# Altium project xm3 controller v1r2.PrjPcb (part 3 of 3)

## Sheet Temperature Sense.SchDoc: Controller
size 492 x 365 mm; OrgAddr3: USA; Page Create Date: March  8, 1995; OrgName: Wolfspeed; OrgAddr1: 535 W Research Center Blvd.; Page Number: 5; Page Size: A; Comment: DualBrandTitleBlock1; Page Count: 8; OrgAddr2: Fayetteville, AR, 72701; Page Name: Temperature Sense; RevCode: V1.2; DsnPath: C:\Users\cnew\Downloads\xm3 controller v1r2-2022-03-14T15-49\xm3 controller v1r2.dsn; SchematicName: SCHEMATIC1; PageName: Temperature Sense; PageSize: A; TopSchematic: True
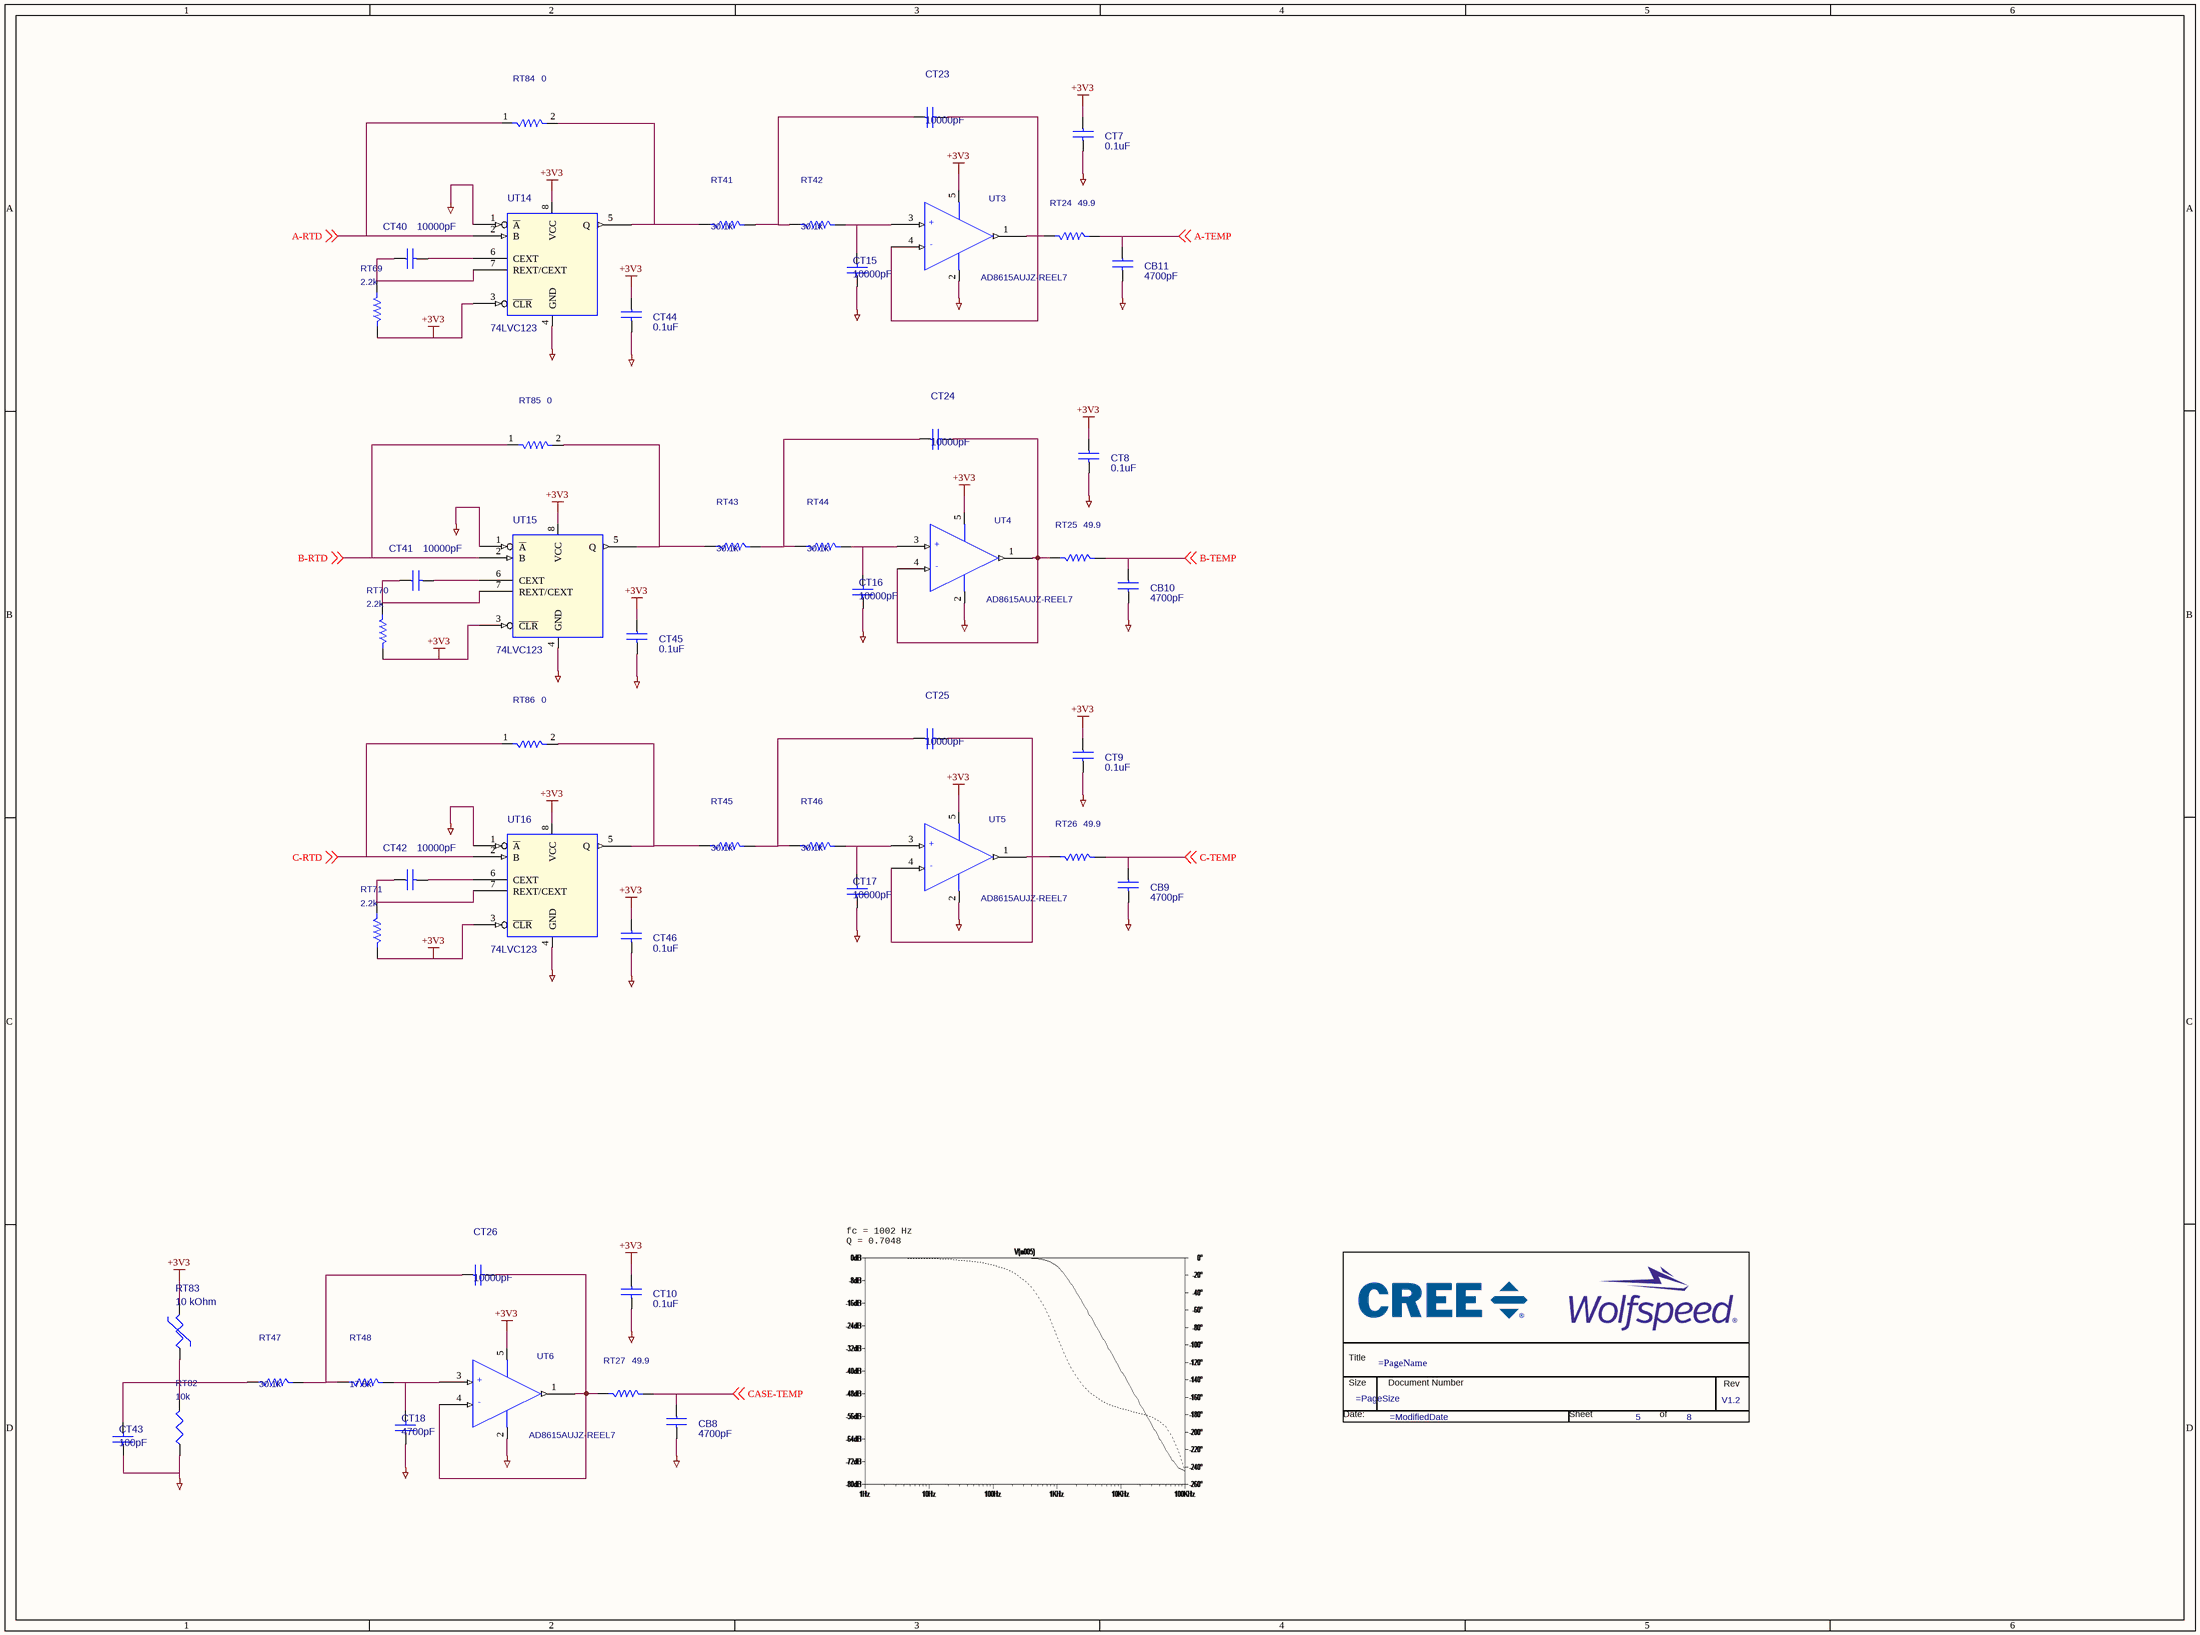
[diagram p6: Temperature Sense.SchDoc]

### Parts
(Parts that share a designator on the sheet are numbered #1, #2 ... from top to bottom, then left to right.)
*#7  Page Count: 8  Page Number: 5  RevCode: V1.2  (hidden comment: DualBrandTitleBlock1)  (graphical)
CB8  4700pF  [c_0603]
CB9  4700pF  [c_0603]
CB10  4700pF  [c_0603]
CB11  4700pF  [c_0603]
CT7  0.1uF  [CAPC1608X87N]
CT8  0.1uF  [CAPC1608X87N]
CT9  0.1uF  [CAPC1608X87N]
CT10  0.1uF  [CAPC1608X87N]
CT15  10000pF  [CAPC1608X90N]
CT16  10000pF  [CAPC1608X90N]
CT17  10000pF  [CAPC1608X90N]
CT18  4700pF  [CAPC1608X90N]
CT23  10000pF  [CAPC1608X90N]
CT24  10000pF  [CAPC1608X90N]
CT25  10000pF  [CAPC1608X90N]
CT26  10000pF  [CAPC1608X90N]
CT40  10000pF  [CAPC1608X90N]
CT41  10000pF  [CAPC1608X90N]
CT42  10000pF  [CAPC1608X90N]
CT43  100pF  [CAPC1608X90N]
CT44  0.1uF  [CAPC1608X87N]
CT45  0.1uF  [CAPC1608X87N]
CT46  0.1uF  [CAPC1608X87N]
RT24  49.9  [RESC1608X55N]
RT25  49.9  [RESC1608X55N]
RT26  49.9  [RESC1608X55N]
RT27  49.9  [RESC1608X55N]
RT41  30.1k  [RESC1608X55N]
RT42  30.1k  [RESC1608X55N]
RT43  30.1k  [RESC1608X55N]
RT44  30.1k  [RESC1608X55N]
RT45  30.1k  [RESC1608X55N]
RT46  30.1k  [RESC1608X55N]
RT47  30.1k  [RESC1608X55N]
RT48  17.8k  [RESC1608X55N]
RT69  2.2k  [RESC1608X55N]
RT70  2.2k  [RESC1608X55N]
RT71  2.2k  [RESC1608X55N]
RT82  10k  [RESC1608X65N]
RT83  10 kOhm  [RESC2012X60N]
RT84  0  [RESC2012X70N]
RT85  0  [RESC2012X70N]
RT86  0  [RESC2012X70N]
UT3  AD8615AUJZ-REEL7  [sot23-5_0_95x2_70p_h1_22]
UT4  AD8615AUJZ-REEL7  [sot23-5_0_95x2_70p_h1_22]
UT5  AD8615AUJZ-REEL7  [sot23-5_0_95x2_70p_h1_22]
UT6  AD8615AUJZ-REEL7  [sot23-5_0_95x2_70p_h1_22]
UT14  74LVC123  [VSSOP8]
UT15  74LVC123  [VSSOP8]
UT16  74LVC123  [VSSOP8]

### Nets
0: CB8.2 CB9.2 CB10.2 CB11.2 CT7.2 CT8.2 CT9.2 CT10.2 CT15.1 CT16.1 CT17.1 CT18.1 CT43.1 CT44.2 CT45.2 CT46.2 RT82.1 UT3.2(V-) UT4.2(V-) UT5.2(V-) UT6.2(V-) UT14.1(~{A}) UT14.4(GND) UT15.1(~{A}) UT15.4(GND) UT16.1(~{A}) UT16.4(GND)
+3V3: CT7.1 CT8.1 CT9.1 CT10.1 CT44.1 CT45.1 CT46.1 RT69.1 RT70.1 RT71.1 RT83.2 UT3.5(V+) UT4.5(V+) UT5.5(V+) UT6.5(V+) UT14.3(~{CLR}) UT14.8(VCC) UT15.3(~{CLR}) UT15.8(VCC) UT16.3(~{CLR}) UT16.8(VCC)
A-RTD: RT84.1 UT14.2(B) ; off-sheet A-RTD
A-TEMP: CB11.1 RT24.2 ; off-sheet A-TEMP
B-RTD: RT85.1 UT15.2(B) ; off-sheet B-RTD
B-TEMP: CB10.1 RT25.2 ; off-sheet B-TEMP
C-RTD: RT86.1 UT16.2(B) ; off-sheet C-RTD
C-TEMP: CB9.1 RT26.2 ; off-sheet C-TEMP
CASE-TEMP: CB8.1 RT27.2 ; off-sheet CASE-TEMP
NetCT15_2: CT15.2 RT42.2 UT3.3(IN+)
NetCT16_2: CT16.2 RT44.2 UT4.3(IN+)
NetCT17_2: CT17.2 RT46.2 UT5.3(IN+)
NetCT18_2: CT18.2 RT48.2 UT6.3(IN+)
NetCT23_1: CT23.1 RT41.2 RT42.1
NetCT23_2: CT23.2 RT24.1 UT3.1(OUT) UT3.4(IN-)
NetCT24_1: CT24.1 RT43.2 RT44.1
NetCT24_2: CT24.2 RT25.1 UT4.1(OUT) UT4.4(IN-)
NetCT25_1: CT25.1 RT45.2 RT46.1
NetCT25_2: CT25.2 RT26.1 UT5.1(OUT) UT5.4(IN-)
NetCT26_1: CT26.1 RT47.2 RT48.1
NetCT26_2: CT26.2 RT27.1 UT6.1(OUT) UT6.4(IN-)
NetCT40_1: CT40.1 RT69.2 UT14.7(REXT/CEXT)
NetCT40_2: CT40.2 UT14.6(CEXT)
NetCT41_1: CT41.1 RT70.2 UT15.7(REXT/CEXT)
NetCT41_2: CT41.2 UT15.6(CEXT)
NetCT42_1: CT42.1 RT71.2 UT16.7(REXT/CEXT)
NetCT42_2: CT42.2 UT16.6(CEXT)
NetCT43_2: CT43.2 RT47.1 RT82.2 RT83.1
NetRT41_1: RT41.1 RT84.2 UT14.5(Q)
NetRT43_1: RT43.1 RT85.2 UT15.5(Q)
NetRT45_1: RT45.1 RT86.2 UT16.5(Q)

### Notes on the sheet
- fc = 1002 Hz
  Q = 0.7048

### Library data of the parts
*#7 = DualBrandTitleBlock1: OrgAddr3: USA; OrgAddr2: Fayetteville, AR, 72701; OrgAddr1: 535 W Research Center Blvd.; OrgName: Wolfspeed; Title: Controller
CB8 = CAP: CAP CER 4700PF 25V X7R 0603; Part Reference: CB8; PART_NUMBER: TMP-889; Manufacturer: Murata Electronics North America; Manufacturer PN: GCM188R71E472KA37D; Company Part Status: New; Dielectric Type: Capacitors; Tolerance: 10%; CLASS: DISCRETE
CB9 = CAP: CAP CER 4700PF 25V X7R 0603; Part Reference: CB9; Manufacturer PN: GCM188R71E472KA37D; Manufacturer: Murata Electronics North America; PART_NUMBER: TMP-889; Company Part Status: New; CLASS: DISCRETE; Tolerance: 10%; Dielectric Type: Capacitors
CB10 = CAP: CAP CER 4700PF 25V X7R 0603; Part Reference: CB10; Manufacturer PN: GCM188R71E472KA37D; Manufacturer: Murata Electronics North America; PART_NUMBER: TMP-889; Company Part Status: New; CLASS: DISCRETE; Tolerance: 10%; Dielectric Type: Capacitors
CB11 = CAP: CAP CER 4700PF 25V X7R 0603; Part Reference: CB11; Manufacturer PN: GCM188R71E472KA37D; Manufacturer: Murata Electronics North America; PART_NUMBER: TMP-889; Company Part Status: New; CLASS: DISCRETE; Tolerance: 10%; Dielectric Type: Capacitors
CT7 = CAP: CAP CER 0.1UF 25V X7R 0603; Part Reference: CT7; PART_NUMBER: TMP-847; Manufacturer: Kemet; Manufacturer PN: C0603C104K3RACTU; Company Part Status: New; Dielectric Type: Capacitors; Tolerance: 10%; CLASS: DISCRETE
CT8 = CAP: CAP CER 0.1UF 25V X7R 0603; Part Reference: CT8; Manufacturer PN: C0603C104K3RACTU; Manufacturer: Kemet; PART_NUMBER: TMP-847; Company Part Status: New; CLASS: DISCRETE; Tolerance: 10%; Dielectric Type: Capacitors
CT9 = CAP: CAP CER 0.1UF 25V X7R 0603; Part Reference: CT9; Manufacturer PN: C0603C104K3RACTU; Manufacturer: Kemet; PART_NUMBER: TMP-847; Company Part Status: New; CLASS: DISCRETE; Tolerance: 10%; Dielectric Type: Capacitors
CT10 = CAP: CAP CER 0.1UF 25V X7R 0603; Part Reference: CT10; PART_NUMBER: TMP-847; Manufacturer: Kemet; Manufacturer PN: C0603C104K3RACTU; Company Part Status: New; Dielectric Type: Capacitors; Tolerance: 10%; CLASS: DISCRETE
CT15 = CAP: CAP CER 10000PF 25V 10% X7R 0603; Part Reference: CT15; Company Part Status: New; Manufacturer PN: CL10B103KA8NNNC; Manufacturer: Samsung Electro-Mechanics America, Inc.; PART_NUMBER: TMP-566; CLASS: DISCRETE; Dielectric Type: Capacitors
CT16 = CAP: CAP CER 10000PF 25V 10% X7R 0603; Part Reference: CT16; Company Part Status: New; PART_NUMBER: TMP-566; Manufacturer: Samsung Electro-Mechanics America, Inc.; Manufacturer PN: CL10B103KA8NNNC; Dielectric Type: Capacitors; CLASS: DISCRETE
CT17 = CAP: CAP CER 10000PF 25V 10% X7R 0603; Part Reference: CT17; Company Part Status: New; PART_NUMBER: TMP-566; Manufacturer: Samsung Electro-Mechanics America, Inc.; Manufacturer PN: CL10B103KA8NNNC; Dielectric Type: Capacitors; CLASS: DISCRETE
CT18 = CAP: CAP CER 4700PF 25V X7R 0603; Part Reference: CT18; Manufacturer PN: GCM188R71E472KA37D; Manufacturer: Murata Electronics North America; PART_NUMBER: TMP-889; CLASS: DISCRETE; Tolerance: 10%; Dielectric Type: Capacitors
CT23 = CAP: CAP CER 10000PF 25V 10% X7R 0603; Part Reference: CT23; Manufacturer PN: CL10B103KA8NNNC; Manufacturer: Samsung Electro-Mechanics America, Inc.; PART_NUMBER: TMP-566; Company Part Status: New; CLASS: DISCRETE; Dielectric Type: Capacitors
CT24 = CAP: CAP CER 10000PF 25V 10% X7R 0603; Part Reference: CT24; PART_NUMBER: TMP-566; Manufacturer: Samsung Electro-Mechanics America, Inc.; Manufacturer PN: CL10B103KA8NNNC; Company Part Status: New; Dielectric Type: Capacitors; CLASS: DISCRETE
CT25 = CAP: CAP CER 10000PF 25V 10% X7R 0603; Part Reference: CT25; PART_NUMBER: TMP-566; Manufacturer: Samsung Electro-Mechanics America, Inc.; Manufacturer PN: CL10B103KA8NNNC; Company Part Status: New; Dielectric Type: Capacitors; CLASS: DISCRETE
CT26 = CAP: CAP CER 10000PF 25V 10% X7R 0603; Part Reference: CT26; Manufacturer PN: CL10B103KA8NNNC; Manufacturer: Samsung Electro-Mechanics America, Inc.; PART_NUMBER: TMP-566; Company Part Status: New; CLASS: DISCRETE; Dielectric Type: Capacitors
CT40 = CAP: CAP CER 10000PF 25V 10% X7R 0603; Part Reference: CT40; PART_NUMBER: TMP-566; Manufacturer: Samsung Electro-Mechanics America, Inc.; Manufacturer PN: CL10B103KA8NNNC; Company Part Status: New; Dielectric Type: Capacitors; CLASS: DISCRETE
CT41 = CAP: CAP CER 10000PF 25V 10% X7R 0603; Part Reference: CT41; PART_NUMBER: TMP-566; Manufacturer: Samsung Electro-Mechanics America, Inc.; Manufacturer PN: CL10B103KA8NNNC; Company Part Status: New; Dielectric Type: Capacitors; CLASS: DISCRETE
CT42 = CAP: CAP CER 10000PF 25V 10% X7R 0603; Part Reference: CT42; PART_NUMBER: TMP-566; Manufacturer: Samsung Electro-Mechanics America, Inc.; Manufacturer PN: CL10B103KA8NNNC; Company Part Status: New; Dielectric Type: Capacitors; CLASS: DISCRETE
CT43 = CAP: CAP CER 100PF 50V 5% NP0 0603; Part Reference: CT43; PART_NUMBER: TMP-455; Manufacturer: Samsung Electro-Mechanics America, Inc; Manufacturer PN: CL10C101JB8NNNC; Company Part Status: New; Dielectric Type: Capacitors; Temperature Coefficient: C0G, NP0; CLASS: DISCRETE
CT44 = CAP: CAP CER 0.1UF 25V X7R 0603; Part Reference: CT44; PART_NUMBER: TMP-847; Manufacturer: Kemet; Manufacturer PN: C0603C104K3RACTU; Company Part Status: New; Dielectric Type: Capacitors; Tolerance: 10%; CLASS: DISCRETE
CT45 = CAP: CAP CER 0.1UF 25V X7R 0603; Part Reference: CT45; PART_NUMBER: TMP-847; Manufacturer: Kemet; Manufacturer PN: C0603C104K3RACTU; Company Part Status: New; Dielectric Type: Capacitors; Tolerance: 10%; CLASS: DISCRETE
CT46 = CAP: CAP CER 0.1UF 25V X7R 0603; Part Reference: CT46; PART_NUMBER: TMP-847; Manufacturer: Kemet; Manufacturer PN: C0603C104K3RACTU; Company Part Status: New; Dielectric Type: Capacitors; Tolerance: 10%; CLASS: DISCRETE
RT24 = RES_Dup1: RES SMD 49.9 OHM 1% 1/10W 0603; Part Reference: RT24; Manufacturer PN: ERJ-3EKF49R9V; Manufacturer: Panasonic Electronic Components; Company Part Status: New; CLASS: DISCRETE; Rated Power: 0.1W, 1/10W; Temperature Coefficient: 100ppm/C
RT25 = RES_Dup1: RES SMD 49.9 OHM 1% 1/10W 0603; Part Reference: RT25; Manufacturer PN: ERJ-3EKF49R9V; Manufacturer: Panasonic Electronic Components; Company Part Status: New; CLASS: DISCRETE; Rated Power: 0.1W, 1/10W; Temperature Coefficient: 100ppm/C
RT26 = RES_Dup1: RES SMD 49.9 OHM 1% 1/10W 0603; Part Reference: RT26; Manufacturer PN: ERJ-3EKF49R9V; Manufacturer: Panasonic Electronic Components; Company Part Status: New; CLASS: DISCRETE; Rated Power: 0.1W, 1/10W; Temperature Coefficient: 100ppm/C
RT27 = RES_Dup1: RES SMD 49.9 OHM 1% 1/10W 0603; Part Reference: RT27; Manufacturer: Panasonic Electronic Components; Manufacturer PN: ERJ-3EKF49R9V; Company Part Status: New; Temperature Coefficient: 100ppm/C; Rated Power: 0.1W, 1/10W; CLASS: DISCRETE
RT41 = RES_Dup1: RES SMD 30.1K OHM 1% 1/10W 0603; Part Reference: RT41; Manufacturer PN: ERJ-3EKF3012V; Manufacturer: Panasonic Electronic Components; PART_NUMBER: TMP-962; Company Part Status: New; CLASS: DISCRETE; Rated Power: 0.1W, 1/10W; Temperature Coefficient: 100ppm/C
RT42 = RES_Dup1: RES SMD 30.1K OHM 1% 1/10W 0603; Part Reference: RT42; Company Part Status: New; Manufacturer PN: ERJ-3EKF3012V; Manufacturer: Panasonic Electronic Components; PART_NUMBER: TMP-962; CLASS: DISCRETE; Rated Power: 0.1W, 1/10W; Temperature Coefficient: 100ppm/C
RT43 = RES_Dup1: RES SMD 30.1K OHM 1% 1/10W 0603; Part Reference: RT43; PART_NUMBER: TMP-962; Manufacturer: Panasonic Electronic Components; Manufacturer PN: ERJ-3EKF3012V; Company Part Status: New; Temperature Coefficient: 100ppm/C; Rated Power: 0.1W, 1/10W; CLASS: DISCRETE
RT44 = RES_Dup1: RES SMD 30.1K OHM 1% 1/10W 0603; Part Reference: RT44; Company Part Status: New; PART_NUMBER: TMP-962; Manufacturer: Panasonic Electronic Components; Manufacturer PN: ERJ-3EKF3012V; Temperature Coefficient: 100ppm/C; Rated Power: 0.1W, 1/10W; CLASS: DISCRETE
RT45 = RES_Dup1: RES SMD 30.1K OHM 1% 1/10W 0603; Part Reference: RT45; PART_NUMBER: TMP-962; Manufacturer: Panasonic Electronic Components; Manufacturer PN: ERJ-3EKF3012V; Company Part Status: New; Temperature Coefficient: 100ppm/C; Rated Power: 0.1W, 1/10W; CLASS: DISCRETE
RT46 = RES_Dup1: RES SMD 30.1K OHM 1% 1/10W 0603; Part Reference: RT46; Company Part Status: New; PART_NUMBER: TMP-962; Manufacturer: Panasonic Electronic Components; Manufacturer PN: ERJ-3EKF3012V; Temperature Coefficient: 100ppm/C; Rated Power: 0.1W, 1/10W; CLASS: DISCRETE
RT47 = RES_Dup1: RES SMD 30.1K OHM 1% 1/10W 0603; Part Reference: RT47; Manufacturer PN: ERJ-3EKF3012V; Manufacturer: Panasonic Electronic Components; PART_NUMBER: TMP-962; Company Part Status: New; CLASS: DISCRETE; Rated Power: 0.1W, 1/10W; Temperature Coefficient: 100ppm/C
RT48 = RES_Dup1: RES SMD 17.8K OHM 1% 1/10W 0603; Part Reference: RT48; Manufacturer PN: ERJ-3EKF1782V; Manufacturer: Panasonic Electronic Components; PART_NUMBER: TMP-995; Company Part Status: Released; CLASS: DISCRETE; Rated Power: 0.1W, 1/10W; Temperature Coefficient: 100ppm/C
RT69 = RES_Dup1: RES SMD 2.2K OHM 1% 1/10W 0603; Part Reference: RT69; Company Part Status: New; Manufacturer: Yageo; Manufacturer PN: RC0603FR-072K2L; Temperature Coefficient: 100ppm/C; Rated Power: 0.1W, 1/10W; CLASS: DISCRETE
RT70 = RES_Dup1: RES SMD 2.2K OHM 1% 1/10W 0603; Part Reference: RT70; Company Part Status: New; Manufacturer: Yageo; Manufacturer PN: RC0603FR-072K2L; Temperature Coefficient: 100ppm/C; Rated Power: 0.1W, 1/10W; CLASS: DISCRETE
RT71 = RES_Dup1: RES SMD 2.2K OHM 1% 1/10W 0603; Part Reference: RT71; Company Part Status: New; Manufacturer: Yageo; Manufacturer PN: RC0603FR-072K2L; Temperature Coefficient: 100ppm/C; Rated Power: 0.1W, 1/10W; CLASS: DISCRETE
RT82 = R: RES SMD 10K OHM 1% 1/10W 0603; Part Reference: RT82; Manufacturer PN: MCR03ERTF1002; Manufacturer: Rohm Semiconductor; PART_NUMBER: TMP-380; Company Part Status: New; CLASS: DISCRETE; Rated Power: 0.1W, 1/10W; Temperature Coefficient: 100ppm/C
RT83 = PTC: THERMISTOR NTC 10KOHM 3900K 0805; Part Reference: RT83; Manufacturer PN: NCP21XV103J03RA; Manufacturer: Murata Electronics North America; Company Part Status: New; CLASS: DISCRETE; Rated Power: 200mW; Tolerance: 5%
RT84 = RES: RES SMD 0 OHM JUMPER 1/8W 0805; Part Reference: RT84; Company Part Status: Released; Manufacturer: Samsung Electro-Mechanics; Manufacturer PN: RC2012J000CS; Rated Power: 0.125W, 1/8W; CLASS: DISCRETE
RT85 = RES: RES SMD 0 OHM JUMPER 1/8W 0805; Part Reference: RT85; Company Part Status: Released; Manufacturer: Samsung Electro-Mechanics; Manufacturer PN: RC2012J000CS; Rated Power: 0.125W, 1/8W; CLASS: DISCRETE
RT86 = RES: RES SMD 0 OHM JUMPER 1/8W 0805; Part Reference: RT86; Company Part Status: Released; Manufacturer: Samsung Electro-Mechanics; Manufacturer PN: RC2012J000CS; Rated Power: 0.125W, 1/8W; CLASS: DISCRETE
UT3 = AD8615: IC OPAMP GP 24MHZ RRO TSOT23-5; Part Reference: UT3; Manufacturer: Analog Devices Inc.; Company Part Status: New; Supply Voltage: 2.7 V - 5.5 V, 1.35 V - 2.75 V
UT4 = AD8615: IC OPAMP GP 24MHZ RRO TSOT23-5; Part Reference: UT4; Company Part Status: New; Manufacturer: Analog Devices Inc.; Supply Voltage: 2.7 V - 5.5 V, 1.35 V - 2.75 V
UT5 = AD8615: IC OPAMP GP 24MHZ RRO TSOT23-5; Part Reference: UT5; Company Part Status: New; Manufacturer: Analog Devices Inc.; Supply Voltage: 2.7 V - 5.5 V, 1.35 V - 2.75 V
UT6 = AD8615: IC OPAMP GP 24MHZ RRO TSOT23-5; Part Reference: UT6; Manufacturer: Analog Devices Inc.; Company Part Status: New; Supply Voltage: 2.7 V - 5.5 V, 1.35 V - 2.75 V
UT14 = 74LVC123: IC SNGLE MONO MULTIVBTOR US8; Part Reference: UT14; Manufacturer PN: SN74LVC1G123DCUR; Manufacturer: Texas Instruments; Company Part Status: New; PCB Footprint: VFSOP-8; Supply Voltage: 1.65V ~ 5.5V
UT15 = 74LVC123: IC SNGLE MONO MULTIVBTOR US8; Part Reference: UT15; Manufacturer PN: SN74LVC1G123DCUR; Manufacturer: Texas Instruments; Company Part Status: New; PCB Footprint: VFSOP-8; Supply Voltage: 1.65V ~ 5.5V
UT16 = 74LVC123: IC SNGLE MONO MULTIVBTOR US8; Part Reference: UT16; Manufacturer PN: SN74LVC1G123DCUR; Manufacturer: Texas Instruments; Company Part Status: New; PCB Footprint: VFSOP-8; Supply Voltage: 1.65V ~ 5.5V

## Sheet Voltage Sense.SchDoc: Controller
size 492 x 365 mm; OrgAddr3: USA; Page Create Date: March  8, 1995; OrgName: Wolfspeed; OrgAddr1: 535 W Research Center Blvd.; Page Number: 4; Page Size: A; Comment: DualBrandTitleBlock1; Page Count: 8; OrgAddr2: Fayetteville, AR, 72701; Page Name: Voltage Sense; RevCode: V1.2; DsnPath: C:\Users\cnew\Downloads\xm3 controller v1r2-2022-03-14T15-49\xm3 controller v1r2.dsn; SchematicName: SCHEMATIC1; PageName: Voltage Sense; PageSize: A; TopSchematic: True
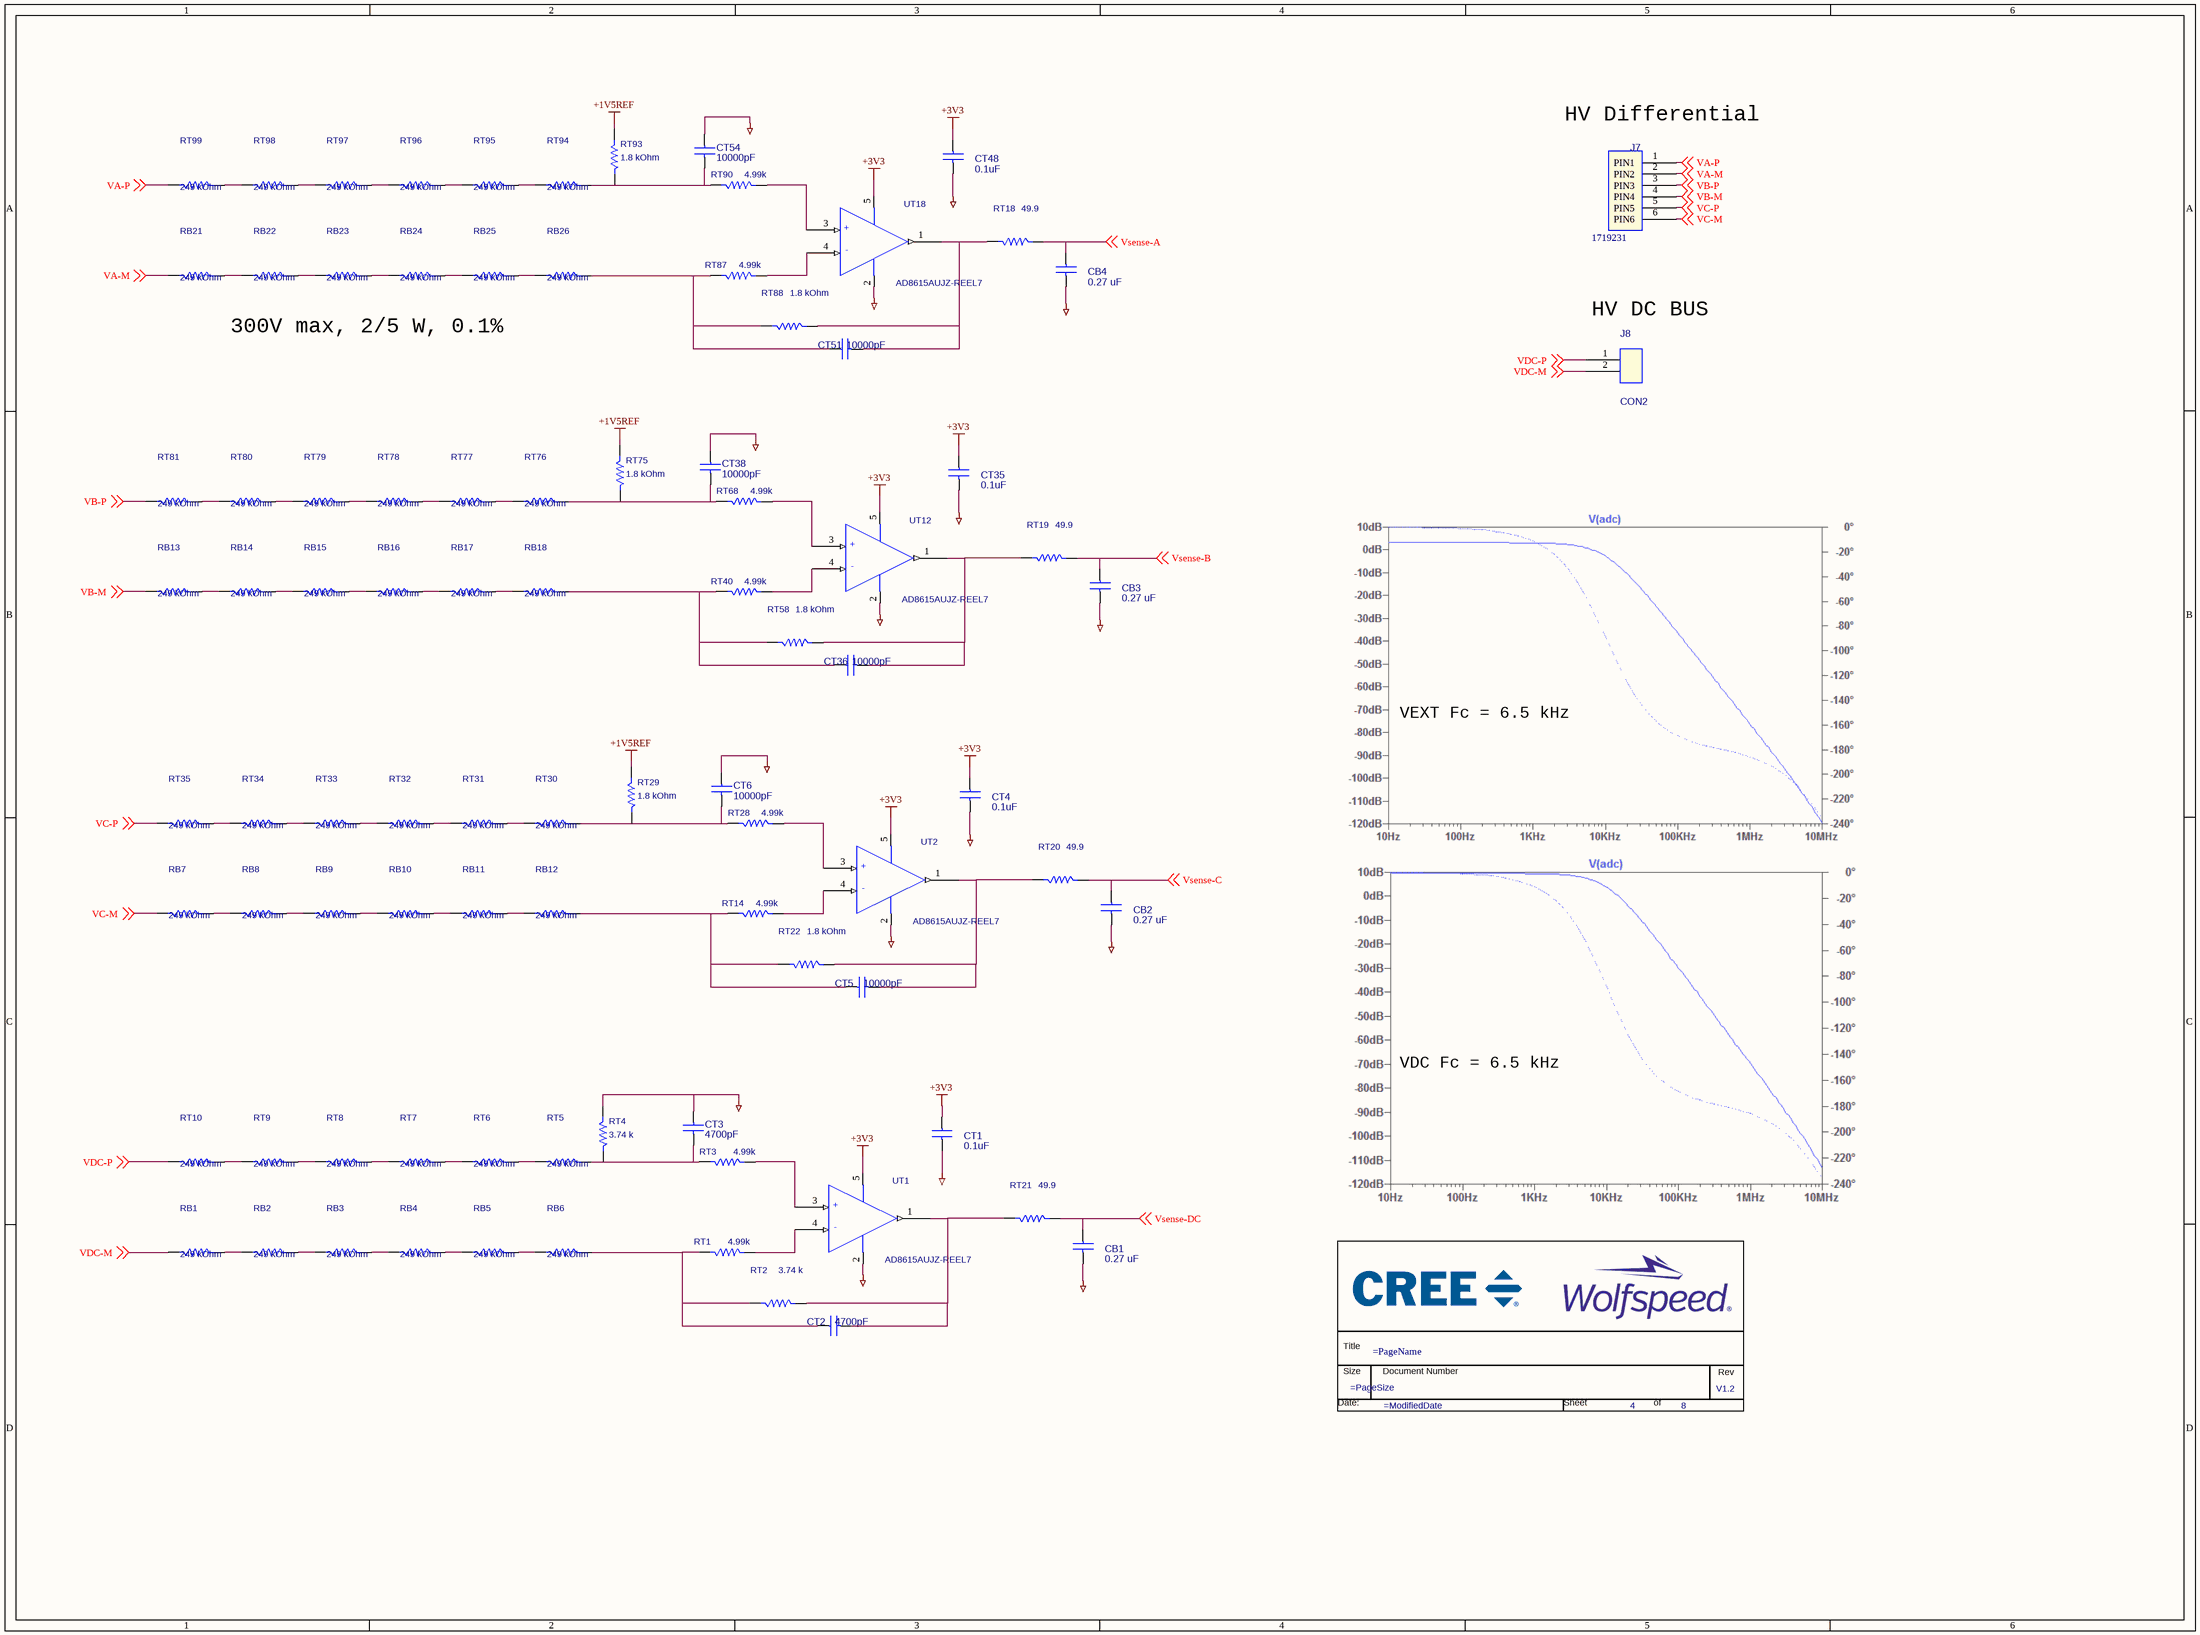
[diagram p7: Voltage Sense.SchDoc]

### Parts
(Parts that share a designator on the sheet are numbered #1, #2 ... from top to bottom, then left to right.)
*#8  Page Count: 8  Page Number: 4  RevCode: V1.2  (hidden comment: DualBrandTitleBlock1)  (graphical)
CB1  0.27 uF  [CAPC1608X90N]
CB2  0.27 uF  [CAPC1608X90N]
CB3  0.27 uF  [CAPC1608X90N]
CB4  0.27 uF  [CAPC1608X90N]
CT1  0.1uF  [CAPC1608X87N]
CT2  4700pF  [CAPC1608X90N]
CT3  4700pF  [CAPC1608X90N]
CT4  0.1uF  [CAPC1608X87N]
CT5  10000pF  [CAPC1608X90N]
CT6  10000pF  [CAPC1608X90N]
CT35  0.1uF  [CAPC1608X87N]
CT36  10000pF  [CAPC1608X90N]
CT38  10000pF  [CAPC1608X90N]
CT48  0.1uF  [CAPC1608X87N]
CT51  10000pF  [CAPC1608X90N]
CT54  10000pF  [CAPC1608X90N]
J7  1719231  [Phoenix_SPT5_6PIN]
J8  CON2  [2POS_400mil_Terminal]
RB1  249 kOhm  [RESC3216X65N]
RB2  249 kOhm  [RESC3216X65N]
RB3  249 kOhm  [RESC3216X65N]
RB4  249 kOhm  [RESC3216X65N]
RB5  249 kOhm  [RESC3216X65N]
RB6  249 kOhm  [RESC3216X65N]
RB7  249 kOhm  [RESC3216X65N]
RB8  249 kOhm  [RESC3216X65N]
RB9  249 kOhm  [RESC3216X65N]
RB10  249 kOhm  [RESC3216X65N]
RB11  249 kOhm  [RESC3216X65N]
RB12  249 kOhm  [RESC3216X65N]
RB13  249 kOhm  [RESC3216X65N]
RB14  249 kOhm  [RESC3216X65N]
RB15  249 kOhm  [RESC3216X65N]
RB16  249 kOhm  [RESC3216X65N]
RB17  249 kOhm  [RESC3216X65N]
RB18  249 kOhm  [RESC3216X65N]
RB21  249 kOhm  [RESC3216X65N]
RB22  249 kOhm  [RESC3216X65N]
RB23  249 kOhm  [RESC3216X65N]
RB24  249 kOhm  [RESC3216X65N]
RB25  249 kOhm  [RESC3216X65N]
RB26  249 kOhm  [RESC3216X65N]
RT1  4.99k  [RESC1608X55N]
RT2  3.74 k  [RESC1608X55N]
RT3  4.99k  [RESC1608X55N]
RT4  3.74 k  [RESC1608X55N]
RT5  249 kOhm  [RESC3216X65N]
RT6  249 kOhm  [RESC3216X65N]
RT7  249 kOhm  [RESC3216X65N]
RT8  249 kOhm  [RESC3216X65N]
RT9  249 kOhm  [RESC3216X65N]
RT10  249 kOhm  [RESC3216X65N]
RT14  4.99k  [RESC1608X55N]
RT18  49.9  [RESC1608X55N]
RT19  49.9  [RESC1608X55N]
RT20  49.9  [RESC1608X55N]
RT21  49.9  [RESC1608X55N]
RT22  1.8 kOhm  [RESC1608X55N]
RT28  4.99k  [RESC1608X55N]
RT29  1.8 kOhm  [RESC1608X55N]
RT30  249 kOhm  [RESC3216X65N]
RT31  249 kOhm  [RESC3216X65N]
RT32  249 kOhm  [RESC3216X65N]
RT33  249 kOhm  [RESC3216X65N]
RT34  249 kOhm  [RESC3216X65N]
RT35  249 kOhm  [RESC3216X65N]
RT40  4.99k  [RESC1608X55N]
RT58  1.8 kOhm  [RESC1608X55N]
RT68  4.99k  [RESC1608X55N]
RT75  1.8 kOhm  [RESC1608X55N]
RT76  249 kOhm  [RESC3216X65N]
RT77  249 kOhm  [RESC3216X65N]
RT78  249 kOhm  [RESC3216X65N]
RT79  249 kOhm  [RESC3216X65N]
RT80  249 kOhm  [RESC3216X65N]
RT81  249 kOhm  [RESC3216X65N]
RT87  4.99k  [RESC1608X55N]
RT88  1.8 kOhm  [RESC1608X55N]
RT90  4.99k  [RESC1608X55N]
RT93  1.8 kOhm  [RESC1608X55N]
RT94  249 kOhm  [RESC3216X65N]
RT95  249 kOhm  [RESC3216X65N]
RT96  249 kOhm  [RESC3216X65N]
RT97  249 kOhm  [RESC3216X65N]
RT98  249 kOhm  [RESC3216X65N]
RT99  249 kOhm  [RESC3216X65N]
UT1  AD8615AUJZ-REEL7  [sot23-5_0_95x2_70p_h1_22]
UT2  AD8615AUJZ-REEL7  [sot23-5_0_95x2_70p_h1_22]
UT12  AD8615AUJZ-REEL7  [sot23-5_0_95x2_70p_h1_22]
UT18  AD8615AUJZ-REEL7  [sot23-5_0_95x2_70p_h1_22]

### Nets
0: CB1.2 CB2.2 CB3.2 CB4.2 CT1.2 CT3.1 CT4.2 CT6.1 CT35.2 CT38.1 CT48.2 CT54.1 RT4.1 UT1.2(V-) UT2.2(V-) UT12.2(V-) UT18.2(V-)
+1V5REF: RT29.1 RT75.1 RT93.1
+3V3: CT1.1 CT4.1 CT35.1 CT48.1 UT1.5(V+) UT2.5(V+) UT12.5(V+) UT18.5(V+)
VA-M: J7.2(PIN2) RB21.1 ; off-sheet VA-M
VA-P: J7.1(PIN1) RT99.1 ; off-sheet VA-P
VB-M: J7.4(PIN4) RB13.1 ; off-sheet VB-M
VB-P: J7.3(PIN3) RT81.1 ; off-sheet VB-P
VC-M: J7.6(PIN6) RB7.1 ; off-sheet VC-M
VC-P: J7.5(PIN5) RT35.1 ; off-sheet VC-P
VDC-M: J8.2 RB1.1 ; off-sheet VDC-M
VDC-P: J8.1 RT10.1 ; off-sheet VDC-P
Vsense-A: CB4.1 RT18.2 ; off-sheet Vsense-A
Vsense-B: CB3.1 RT19.2 ; off-sheet Vsense-B
Vsense-C: CB2.1 RT20.2 ; off-sheet Vsense-C
Vsense-DC: CB1.1 RT21.2 ; off-sheet Vsense-DC
NetCT2_1: CT2.1 RB6.2 RT1.1 RT2.1
NetCT2_2: CT2.2 RT2.2 RT21.1 UT1.1(OUT)
NetCT3_2: CT3.2 RT3.1 RT4.2 RT5.2
NetCT5_1: CT5.1 RB12.2 RT14.1 RT22.1
NetCT5_2: CT5.2 RT20.1 RT22.2 UT2.1(OUT)
NetCT6_2: CT6.2 RT28.1 RT29.2 RT30.2
NetCT36_1: CT36.1 RB18.2 RT40.1 RT58.1
NetCT36_2: CT36.2 RT19.1 RT58.2 UT12.1(OUT)
NetCT38_2: CT38.2 RT68.1 RT75.2 RT76.2
NetCT51_1: CT51.1 RB26.2 RT87.1 RT88.1
NetCT51_2: CT51.2 RT18.1 RT88.2 UT18.1(OUT)
NetCT54_2: CT54.2 RT90.1 RT93.2 RT94.2
NetRB1_2: RB1.2 RB2.1
NetRB2_2: RB2.2 RB3.1
NetRB3_2: RB3.2 RB4.1
NetRB4_2: RB4.2 RB5.1
NetRB5_2: RB5.2 RB6.1
NetRB7_2: RB7.2 RB8.1
NetRB8_2: RB8.2 RB9.1
NetRB9_2: RB9.2 RB10.1
NetRB10_2: RB10.2 RB11.1
NetRB11_2: RB11.2 RB12.1
NetRB13_2: RB13.2 RB14.1
NetRB14_2: RB14.2 RB15.1
NetRB15_2: RB15.2 RB16.1
NetRB16_2: RB16.2 RB17.1
NetRB17_2: RB17.2 RB18.1
NetRB21_2: RB21.2 RB22.1
NetRB22_2: RB22.2 RB23.1
NetRB23_2: RB23.2 RB24.1
NetRB24_2: RB24.2 RB25.1
NetRB25_2: RB25.2 RB26.1
NetRT1_2: RT1.2 UT1.4(IN-)
NetRT3_2: RT3.2 UT1.3(IN+)
NetRT5_1: RT5.1 RT6.2
NetRT6_1: RT6.1 RT7.2
NetRT7_1: RT7.1 RT8.2
NetRT8_1: RT8.1 RT9.2
NetRT9_1: RT9.1 RT10.2
NetRT14_2: RT14.2 UT2.4(IN-)
NetRT28_2: RT28.2 UT2.3(IN+)
NetRT30_1: RT30.1 RT31.2
NetRT31_1: RT31.1 RT32.2
NetRT32_1: RT32.1 RT33.2
NetRT33_1: RT33.1 RT34.2
NetRT34_1: RT34.1 RT35.2
NetRT40_2: RT40.2 UT12.4(IN-)
NetRT68_2: RT68.2 UT12.3(IN+)
NetRT76_1: RT76.1 RT77.2
NetRT77_1: RT77.1 RT78.2
NetRT78_1: RT78.1 RT79.2
NetRT79_1: RT79.1 RT80.2
NetRT80_1: RT80.1 RT81.2
NetRT87_2: RT87.2 UT18.4(IN-)
NetRT90_2: RT90.2 UT18.3(IN+)
NetRT94_1: RT94.1 RT95.2
NetRT95_1: RT95.1 RT96.2
NetRT96_1: RT96.1 RT97.2
NetRT97_1: RT97.1 RT98.2
NetRT98_1: RT98.1 RT99.2

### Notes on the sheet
- (near J7) HV Differential
- 300V max, 2/5 W, 0.1%
- (near J8) HV DC BUS
- VEXT Fc = 6.5 kHz
- VDC Fc = 6.5 kHz

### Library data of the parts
*#8 = DualBrandTitleBlock1: as *#7 on sheet Temperature Sense
CB1 = CAP: CAP CER 0.27UF 16V X7R 0603; Part Reference: CB1; Manufacturer PN: GCM188R71C274KA37D; Manufacturer: Murata Electronics North America; Company Part Status: New; CLASS: DISCRETE; Tolerance: 10%; Dielectric Type: Capacitors
CB2 = CAP: CAP CER 0.27UF 16V X7R 0603; Part Reference: CB2; Manufacturer PN: GCM188R71C274KA37D; Manufacturer: Murata Electronics North America; Company Part Status: New; CLASS: DISCRETE; Tolerance: 10%; Dielectric Type: Capacitors
CB3 = CAP: CAP CER 0.27UF 16V X7R 0603; Part Reference: CB3; Manufacturer PN: GCM188R71C274KA37D; Manufacturer: Murata Electronics North America; Company Part Status: New; CLASS: DISCRETE; Tolerance: 10%; Dielectric Type: Capacitors
CB4 = CAP: CAP CER 0.27UF 16V X7R 0603; Part Reference: CB4; Manufacturer PN: GCM188R71C274KA37D; Manufacturer: Murata Electronics North America; Company Part Status: New; CLASS: DISCRETE; Tolerance: 10%; Dielectric Type: Capacitors
CT1 = CAP: CAP CER 0.1UF 25V X7R 0603; Part Reference: CT1; Manufacturer PN: C0603C104K3RACTU; Manufacturer: Kemet; PART_NUMBER: TMP-847; Company Part Status: New; CLASS: DISCRETE; Tolerance: 10%; Dielectric Type: Capacitors
CT2 = CAP: CAP CER 4700PF 25V X7R 0603; Part Reference: CT2; Manufacturer PN: GCM188R71E472KA37D; Manufacturer: Murata Electronics North America; PART_NUMBER: TMP-889; CLASS: DISCRETE; Tolerance: 10%; Dielectric Type: Capacitors
CT3 = CAP: CAP CER 4700PF 25V X7R 0603; Part Reference: CT3; Manufacturer PN: GCM188R71E472KA37D; Manufacturer: Murata Electronics North America; PART_NUMBER: TMP-889; CLASS: DISCRETE; Tolerance: 10%; Dielectric Type: Capacitors
CT4 = CAP: CAP CER 0.1UF 25V X7R 0603; Part Reference: CT4; Manufacturer PN: C0603C104K3RACTU; Manufacturer: Kemet; PART_NUMBER: TMP-847; Company Part Status: New; CLASS: DISCRETE; Tolerance: 10%; Dielectric Type: Capacitors
CT5 = CAP: CAP CER 10000PF 25V 10% X7R 0603; Part Reference: CT5; PART_NUMBER: TMP-566; Manufacturer: Samsung Electro-Mechanics America, Inc.; Manufacturer PN: CL10B103KA8NNNC; Company Part Status: New; Dielectric Type: Capacitors; CLASS: DISCRETE
CT6 = CAP: CAP CER 10000PF 25V 10% X7R 0603; Part Reference: CT6; Manufacturer PN: CL10B103KA8NNNC; Manufacturer: Samsung Electro-Mechanics America, Inc.; PART_NUMBER: TMP-566; Company Part Status: New; CLASS: DISCRETE; Dielectric Type: Capacitors
CT35 = CAP: CAP CER 0.1UF 25V X7R 0603; Part Reference: CT35; Manufacturer PN: C0603C104K3RACTU; Manufacturer: Kemet; PART_NUMBER: TMP-847; Company Part Status: New; CLASS: DISCRETE; Tolerance: 10%; Dielectric Type: Capacitors
CT36 = CAP: CAP CER 10000PF 25V 10% X7R 0603; Part Reference: CT36; PART_NUMBER: TMP-566; Manufacturer: Samsung Electro-Mechanics America, Inc.; Manufacturer PN: CL10B103KA8NNNC; Company Part Status: New; Dielectric Type: Capacitors; CLASS: DISCRETE
CT38 = CAP: CAP CER 10000PF 25V 10% X7R 0603; Part Reference: CT38; Manufacturer PN: CL10B103KA8NNNC; Manufacturer: Samsung Electro-Mechanics America, Inc.; PART_NUMBER: TMP-566; Company Part Status: New; CLASS: DISCRETE; Dielectric Type: Capacitors
CT48 = CAP: CAP CER 0.1UF 25V X7R 0603; Part Reference: CT48; PART_NUMBER: TMP-847; Manufacturer: Kemet; Manufacturer PN: C0603C104K3RACTU; Company Part Status: New; Dielectric Type: Capacitors; Tolerance: 10%; CLASS: DISCRETE
CT51 = CAP: CAP CER 10000PF 25V 10% X7R 0603; Part Reference: CT51; Manufacturer PN: CL10B103KA8NNNC; Manufacturer: Samsung Electro-Mechanics America, Inc.; PART_NUMBER: TMP-566; Company Part Status: New; CLASS: DISCRETE; Dielectric Type: Capacitors
CT54 = CAP: CAP CER 10000PF 25V 10% X7R 0603; Part Reference: CT54; PART_NUMBER: TMP-566; Manufacturer: Samsung Electro-Mechanics America, Inc.; Manufacturer PN: CL10B103KA8NNNC; Company Part Status: New; Dielectric Type: Capacitors; CLASS: DISCRETE
J7 = HDR_1X6_M: TERM BLK 6POS SIDE ENT 7.5MM PCB; Part Reference: J7; Company Part Status: New; Manufacturer: Phoenix Contact; CLASS: IO; Contact Voltage: 1000 V
J8 = CON2: Part Reference: J8
RB1 = RES_Dup1: RES 249K OHM 0.1% 2/5W 1206; Part Reference: RB1; Manufacturer PN: TNPW1206249KBEEA; Manufacturer: Vishay Dale; Company Part Status: New; CLASS: DISCRETE; Rated Power: 0.4W, 2/5W; Temperature Coefficient: 25ppm/C
RB2 = RES_Dup1: RES 249K OHM 0.1% 2/5W 1206; Part Reference: RB2; Manufacturer PN: TNPW1206249KBEEA; Manufacturer: Vishay Dale; Company Part Status: New; CLASS: DISCRETE; Rated Power: 0.4W, 2/5W; Temperature Coefficient: 25ppm/C
RB3 = RES_Dup1: RES 249K OHM 0.1% 2/5W 1206; Part Reference: RB3; Manufacturer PN: TNPW1206249KBEEA; Manufacturer: Vishay Dale; Company Part Status: New; CLASS: DISCRETE; Rated Power: 0.4W, 2/5W; Temperature Coefficient: 25ppm/C
RB4 = RES_Dup1: RES 249K OHM 0.1% 2/5W 1206; Part Reference: RB4; Manufacturer PN: TNPW1206249KBEEA; Manufacturer: Vishay Dale; Company Part Status: New; CLASS: DISCRETE; Rated Power: 0.4W, 2/5W; Temperature Coefficient: 25ppm/C
RB5 = RES_Dup1: RES 249K OHM 0.1% 2/5W 1206; Part Reference: RB5; Manufacturer PN: TNPW1206249KBEEA; Manufacturer: Vishay Dale; Company Part Status: New; CLASS: DISCRETE; Rated Power: 0.4W, 2/5W; Temperature Coefficient: 25ppm/C
RB6 = RES_Dup1: RES 249K OHM 0.1% 2/5W 1206; Part Reference: RB6; Manufacturer PN: TNPW1206249KBEEA; Manufacturer: Vishay Dale; Company Part Status: New; CLASS: DISCRETE; Rated Power: 0.4W, 2/5W; Temperature Coefficient: 25ppm/C
RB7 = RES_Dup1: RES 249K OHM 0.1% 2/5W 1206; Part Reference: RB7; Manufacturer PN: TNPW1206249KBEEA; Manufacturer: Vishay Dale; Company Part Status: New; CLASS: DISCRETE; Rated Power: 0.4W, 2/5W; Temperature Coefficient: 25ppm/C
RB8 = RES_Dup1: RES 249K OHM 0.1% 2/5W 1206; Part Reference: RB8; Manufacturer PN: TNPW1206249KBEEA; Manufacturer: Vishay Dale; Company Part Status: New; CLASS: DISCRETE; Rated Power: 0.4W, 2/5W; Temperature Coefficient: 25ppm/C
RB9 = RES_Dup1: RES 249K OHM 0.1% 2/5W 1206; Part Reference: RB9; Manufacturer PN: TNPW1206249KBEEA; Manufacturer: Vishay Dale; Company Part Status: New; CLASS: DISCRETE; Rated Power: 0.4W, 2/5W; Temperature Coefficient: 25ppm/C
RB10 = RES_Dup1: RES 249K OHM 0.1% 2/5W 1206; Part Reference: RB10; Manufacturer PN: TNPW1206249KBEEA; Manufacturer: Vishay Dale; Company Part Status: New; CLASS: DISCRETE; Rated Power: 0.4W, 2/5W; Temperature Coefficient: 25ppm/C
RB11 = RES_Dup1: RES 249K OHM 0.1% 2/5W 1206; Part Reference: RB11; Manufacturer PN: TNPW1206249KBEEA; Manufacturer: Vishay Dale; Company Part Status: New; CLASS: DISCRETE; Rated Power: 0.4W, 2/5W; Temperature Coefficient: 25ppm/C
RB12 = RES_Dup1: RES 249K OHM 0.1% 2/5W 1206; Part Reference: RB12; Manufacturer PN: TNPW1206249KBEEA; Manufacturer: Vishay Dale; Company Part Status: New; CLASS: DISCRETE; Rated Power: 0.4W, 2/5W; Temperature Coefficient: 25ppm/C
RB13 = RES_Dup1: RES 249K OHM 0.1% 2/5W 1206; Part Reference: RB13; Manufacturer PN: TNPW1206249KBEEA; Manufacturer: Vishay Dale; Company Part Status: New; CLASS: DISCRETE; Rated Power: 0.4W, 2/5W; Temperature Coefficient: 25ppm/C
RB14 = RES_Dup1: RES 249K OHM 0.1% 2/5W 1206; Part Reference: RB14; Manufacturer PN: TNPW1206249KBEEA; Manufacturer: Vishay Dale; Company Part Status: New; CLASS: DISCRETE; Rated Power: 0.4W, 2/5W; Temperature Coefficient: 25ppm/C
RB15 = RES_Dup1: RES 249K OHM 0.1% 2/5W 1206; Part Reference: RB15; Manufacturer PN: TNPW1206249KBEEA; Manufacturer: Vishay Dale; Company Part Status: New; CLASS: DISCRETE; Rated Power: 0.4W, 2/5W; Temperature Coefficient: 25ppm/C
RB16 = RES_Dup1: RES 249K OHM 0.1% 2/5W 1206; Part Reference: RB16; Manufacturer PN: TNPW1206249KBEEA; Manufacturer: Vishay Dale; Company Part Status: New; CLASS: DISCRETE; Rated Power: 0.4W, 2/5W; Temperature Coefficient: 25ppm/C
RB17 = RES_Dup1: RES 249K OHM 0.1% 2/5W 1206; Part Reference: RB17; Manufacturer PN: TNPW1206249KBEEA; Manufacturer: Vishay Dale; Company Part Status: New; CLASS: DISCRETE; Rated Power: 0.4W, 2/5W; Temperature Coefficient: 25ppm/C
RB18 = RES_Dup1: RES 249K OHM 0.1% 2/5W 1206; Part Reference: RB18; Manufacturer PN: TNPW1206249KBEEA; Manufacturer: Vishay Dale; Company Part Status: New; CLASS: DISCRETE; Rated Power: 0.4W, 2/5W; Temperature Coefficient: 25ppm/C
RB21 = RES_Dup1: RES 249K OHM 0.1% 2/5W 1206; Part Reference: RB21; Manufacturer PN: TNPW1206249KBEEA; Manufacturer: Vishay Dale; Company Part Status: New; CLASS: DISCRETE; Rated Power: 0.4W, 2/5W; Temperature Coefficient: 25ppm/C
RB22 = RES_Dup1: RES 249K OHM 0.1% 2/5W 1206; Part Reference: RB22; Manufacturer PN: TNPW1206249KBEEA; Manufacturer: Vishay Dale; Company Part Status: New; CLASS: DISCRETE; Rated Power: 0.4W, 2/5W; Temperature Coefficient: 25ppm/C
RB23 = RES_Dup1: RES 249K OHM 0.1% 2/5W 1206; Part Reference: RB23; Manufacturer PN: TNPW1206249KBEEA; Manufacturer: Vishay Dale; Company Part Status: New; CLASS: DISCRETE; Rated Power: 0.4W, 2/5W; Temperature Coefficient: 25ppm/C
RB24 = RES_Dup1: RES 249K OHM 0.1% 2/5W 1206; Part Reference: RB24; Manufacturer PN: TNPW1206249KBEEA; Manufacturer: Vishay Dale; Company Part Status: New; CLASS: DISCRETE; Rated Power: 0.4W, 2/5W; Temperature Coefficient: 25ppm/C
RB25 = RES_Dup1: RES 249K OHM 0.1% 2/5W 1206; Part Reference: RB25; Manufacturer PN: TNPW1206249KBEEA; Manufacturer: Vishay Dale; Company Part Status: New; CLASS: DISCRETE; Rated Power: 0.4W, 2/5W; Temperature Coefficient: 25ppm/C
RB26 = RES_Dup1: RES 249K OHM 0.1% 2/5W 1206; Part Reference: RB26; Manufacturer PN: TNPW1206249KBEEA; Manufacturer: Vishay Dale; Company Part Status: New; CLASS: DISCRETE; Rated Power: 0.4W, 2/5W; Temperature Coefficient: 25ppm/C
RT1 = RES_Dup1: RES SMD 4.99K OHM 1% 1/10W 0603; Part Reference: RT1; PART_NUMBER: TMP-871; Manufacturer: Yageo; Manufacturer PN: RC0603FR-074K99L; Company Part Status: Released; Temperature Coefficient: 100ppm/C; Rated Power: 0.1W, 1/10W; CLASS: DISCRETE
RT2 = RES_Dup1: RES SMD 3.74K OHM 0.1% 1/5W 0603; Part Reference: RT2; Manufacturer: Panasonic Electronic Components; Manufacturer PN: ERJ-PB3B3741V; Company Part Status: New; Temperature Coefficient: 50ppm/C; Rated Power: 0.2W, 1/5W; CLASS: DISCRETE
RT3 = RES_Dup1: RES SMD 4.99K OHM 1% 1/10W 0603; Part Reference: RT3; PART_NUMBER: TMP-871; Manufacturer: Yageo; Manufacturer PN: RC0603FR-074K99L; Company Part Status: Released; Temperature Coefficient: 100ppm/C; Rated Power: 0.1W, 1/10W; CLASS: DISCRETE
RT4 = RES_Dup1: RES SMD 3.74K OHM 0.1% 1/5W 0603; Part Reference: RT4; Manufacturer: Panasonic Electronic Components; Manufacturer PN: ERJ-PB3B3741V; Company Part Status: New; Temperature Coefficient: 50ppm/C; Rated Power: 0.2W, 1/5W; CLASS: DISCRETE
RT5 = RES_Dup1: RES 249K OHM 0.1% 2/5W 1206; Part Reference: RT5; Manufacturer PN: TNPW1206249KBEEA; Manufacturer: Vishay Dale; Company Part Status: New; CLASS: DISCRETE; Rated Power: 0.4W, 2/5W; Temperature Coefficient: 25ppm/C
RT6 = RES_Dup1: RES 249K OHM 0.1% 2/5W 1206; Part Reference: RT6; Manufacturer PN: TNPW1206249KBEEA; Manufacturer: Vishay Dale; Company Part Status: New; CLASS: DISCRETE; Rated Power: 0.4W, 2/5W; Temperature Coefficient: 25ppm/C
RT7 = RES_Dup1: RES 249K OHM 0.1% 2/5W 1206; Part Reference: RT7; Manufacturer PN: TNPW1206249KBEEA; Manufacturer: Vishay Dale; Company Part Status: New; CLASS: DISCRETE; Rated Power: 0.4W, 2/5W; Temperature Coefficient: 25ppm/C
RT8 = RES_Dup1: RES 249K OHM 0.1% 2/5W 1206; Part Reference: RT8; Manufacturer PN: TNPW1206249KBEEA; Manufacturer: Vishay Dale; Company Part Status: New; CLASS: DISCRETE; Rated Power: 0.4W, 2/5W; Temperature Coefficient: 25ppm/C
RT9 = RES_Dup1: RES 249K OHM 0.1% 2/5W 1206; Part Reference: RT9; Manufacturer PN: TNPW1206249KBEEA; Manufacturer: Vishay Dale; Company Part Status: New; CLASS: DISCRETE; Rated Power: 0.4W, 2/5W; Temperature Coefficient: 25ppm/C
RT10 = RES_Dup1: RES 249K OHM 0.1% 2/5W 1206; Part Reference: RT10; Manufacturer PN: TNPW1206249KBEEA; Manufacturer: Vishay Dale; Company Part Status: New; CLASS: DISCRETE; Rated Power: 0.4W, 2/5W; Temperature Coefficient: 25ppm/C
RT14 = RES_Dup1: RES SMD 4.99K OHM 1% 1/10W 0603; Part Reference: RT14; PART_NUMBER: TMP-871; Manufacturer: Yageo; Manufacturer PN: RC0603FR-074K99L; Company Part Status: Released; Temperature Coefficient: 100ppm/C; Rated Power: 0.1W, 1/10W; CLASS: DISCRETE
RT18 = RES_Dup1: RES SMD 49.9 OHM 1% 1/10W 0603; Part Reference: RT18; Manufacturer PN: ERJ-3EKF49R9V; Manufacturer: Panasonic Electronic Components; Company Part Status: New; CLASS: DISCRETE; Rated Power: 0.1W, 1/10W; Temperature Coefficient: 100ppm/C
RT19 = RES_Dup1: RES SMD 49.9 OHM 1% 1/10W 0603; Part Reference: RT19; Manufacturer PN: ERJ-3EKF49R9V; Manufacturer: Panasonic Electronic Components; Company Part Status: New; CLASS: DISCRETE; Rated Power: 0.1W, 1/10W; Temperature Coefficient: 100ppm/C
RT20 = RES_Dup1: RES SMD 49.9 OHM 1% 1/10W 0603; Part Reference: RT20; Manufacturer PN: ERJ-3EKF49R9V; Manufacturer: Panasonic Electronic Components; Company Part Status: New; CLASS: DISCRETE; Rated Power: 0.1W, 1/10W; Temperature Coefficient: 100ppm/C
RT21 = RES_Dup1: RES SMD 49.9 OHM 1% 1/10W 0603; Part Reference: RT21; Manufacturer PN: ERJ-3EKF49R9V; Manufacturer: Panasonic Electronic Components; Company Part Status: New; CLASS: DISCRETE; Rated Power: 0.1W, 1/10W; Temperature Coefficient: 100ppm/C
RT22 = RES_Dup1: RES SMD 1.8K OHM 0.1% 1/5W 0603; Part Reference: RT22; Manufacturer PN: ERJ-PB3B1801V; Manufacturer: Panasonic Electronic Components; Company Part Status: New; CLASS: DISCRETE; Rated Power: 0.2W, 1/5W; Temperature Coefficient: 50ppm/C
RT28 = RES_Dup1: RES SMD 4.99K OHM 1% 1/10W 0603; Part Reference: RT28; PART_NUMBER: TMP-871; Manufacturer: Yageo; Manufacturer PN: RC0603FR-074K99L; Company Part Status: Released; Temperature Coefficient: 100ppm/C; Rated Power: 0.1W, 1/10W; CLASS: DISCRETE
RT29 = RES_Dup1: RES SMD 1.8K OHM 0.1% 1/5W 0603; Part Reference: RT29; Manufacturer: Panasonic Electronic Components; Manufacturer PN: ERJ-PB3B1801V; Company Part Status: New; Temperature Coefficient: 50ppm/C; Rated Power: 0.2W, 1/5W; CLASS: DISCRETE
RT30 = RES_Dup1: RES 249K OHM 0.1% 2/5W 1206; Part Reference: RT30; Manufacturer PN: TNPW1206249KBEEA; Manufacturer: Vishay Dale; Company Part Status: New; CLASS: DISCRETE; Rated Power: 0.4W, 2/5W; Temperature Coefficient: 25ppm/C
RT31 = RES_Dup1: RES 249K OHM 0.1% 2/5W 1206; Part Reference: RT31; Manufacturer PN: TNPW1206249KBEEA; Manufacturer: Vishay Dale; Company Part Status: New; CLASS: DISCRETE; Rated Power: 0.4W, 2/5W; Temperature Coefficient: 25ppm/C
RT32 = RES_Dup1: RES 249K OHM 0.1% 2/5W 1206; Part Reference: RT32; Manufacturer PN: TNPW1206249KBEEA; Manufacturer: Vishay Dale; Company Part Status: New; CLASS: DISCRETE; Rated Power: 0.4W, 2/5W; Temperature Coefficient: 25ppm/C
RT33 = RES_Dup1: RES 249K OHM 0.1% 2/5W 1206; Part Reference: RT33; Manufacturer PN: TNPW1206249KBEEA; Manufacturer: Vishay Dale; Company Part Status: New; CLASS: DISCRETE; Rated Power: 0.4W, 2/5W; Temperature Coefficient: 25ppm/C
RT34 = RES_Dup1: RES 249K OHM 0.1% 2/5W 1206; Part Reference: RT34; Manufacturer PN: TNPW1206249KBEEA; Manufacturer: Vishay Dale; Company Part Status: New; CLASS: DISCRETE; Rated Power: 0.4W, 2/5W; Temperature Coefficient: 25ppm/C
RT35 = RES_Dup1: RES 249K OHM 0.1% 2/5W 1206; Part Reference: RT35; Manufacturer PN: TNPW1206249KBEEA; Manufacturer: Vishay Dale; Company Part Status: New; CLASS: DISCRETE; Rated Power: 0.4W, 2/5W; Temperature Coefficient: 25ppm/C
RT40 = RES_Dup1: RES SMD 4.99K OHM 1% 1/10W 0603; Part Reference: RT40; PART_NUMBER: TMP-871; Manufacturer: Yageo; Manufacturer PN: RC0603FR-074K99L; Company Part Status: Released; Temperature Coefficient: 100ppm/C; Rated Power: 0.1W, 1/10W; CLASS: DISCRETE
RT58 = RES_Dup1: RES SMD 1.8K OHM 0.1% 1/5W 0603; Part Reference: RT58; Manufacturer PN: ERJ-PB3B1801V; Manufacturer: Panasonic Electronic Components; Company Part Status: New; CLASS: DISCRETE; Rated Power: 0.2W, 1/5W; Temperature Coefficient: 50ppm/C
RT68 = RES_Dup1: RES SMD 4.99K OHM 1% 1/10W 0603; Part Reference: RT68; PART_NUMBER: TMP-871; Manufacturer: Yageo; Manufacturer PN: RC0603FR-074K99L; Company Part Status: Released; Temperature Coefficient: 100ppm/C; Rated Power: 0.1W, 1/10W; CLASS: DISCRETE
RT75 = RES_Dup1: RES SMD 1.8K OHM 0.1% 1/5W 0603; Part Reference: RT75; Manufacturer: Panasonic Electronic Components; Manufacturer PN: ERJ-PB3B1801V; Company Part Status: New; Temperature Coefficient: 50ppm/C; Rated Power: 0.2W, 1/5W; CLASS: DISCRETE
RT76 = RES_Dup1: RES 249K OHM 0.1% 2/5W 1206; Part Reference: RT76; Manufacturer PN: TNPW1206249KBEEA; Manufacturer: Vishay Dale; Company Part Status: New; CLASS: DISCRETE; Rated Power: 0.4W, 2/5W; Temperature Coefficient: 25ppm/C
RT77 = RES_Dup1: RES 249K OHM 0.1% 2/5W 1206; Part Reference: RT77; Manufacturer PN: TNPW1206249KBEEA; Manufacturer: Vishay Dale; Company Part Status: New; CLASS: DISCRETE; Rated Power: 0.4W, 2/5W; Temperature Coefficient: 25ppm/C
RT78 = RES_Dup1: RES 249K OHM 0.1% 2/5W 1206; Part Reference: RT78; Manufacturer PN: TNPW1206249KBEEA; Manufacturer: Vishay Dale; Company Part Status: New; CLASS: DISCRETE; Rated Power: 0.4W, 2/5W; Temperature Coefficient: 25ppm/C
RT79 = RES_Dup1: RES 249K OHM 0.1% 2/5W 1206; Part Reference: RT79; Manufacturer PN: TNPW1206249KBEEA; Manufacturer: Vishay Dale; Company Part Status: New; CLASS: DISCRETE; Rated Power: 0.4W, 2/5W; Temperature Coefficient: 25ppm/C
RT80 = RES_Dup1: RES 249K OHM 0.1% 2/5W 1206; Part Reference: RT80; Manufacturer PN: TNPW1206249KBEEA; Manufacturer: Vishay Dale; Company Part Status: New; CLASS: DISCRETE; Rated Power: 0.4W, 2/5W; Temperature Coefficient: 25ppm/C
RT81 = RES_Dup1: RES 249K OHM 0.1% 2/5W 1206; Part Reference: RT81; Manufacturer PN: TNPW1206249KBEEA; Manufacturer: Vishay Dale; Company Part Status: New; CLASS: DISCRETE; Rated Power: 0.4W, 2/5W; Temperature Coefficient: 25ppm/C
RT87 = RES_Dup1: RES SMD 4.99K OHM 1% 1/10W 0603; Part Reference: RT87; Manufacturer PN: RC0603FR-074K99L; Manufacturer: Yageo; PART_NUMBER: TMP-871; Company Part Status: Released; CLASS: DISCRETE; Rated Power: 0.1W, 1/10W; Temperature Coefficient: 100ppm/C
RT88 = RES_Dup1: RES SMD 1.8K OHM 0.1% 1/5W 0603; Part Reference: RT88; Manufacturer: Panasonic Electronic Components; Manufacturer PN: ERJ-PB3B1801V; Company Part Status: New; Temperature Coefficient: 50ppm/C; Rated Power: 0.2W, 1/5W; CLASS: DISCRETE
RT90 = RES_Dup1: RES SMD 4.99K OHM 1% 1/10W 0603; Part Reference: RT90; Manufacturer PN: RC0603FR-074K99L; Manufacturer: Yageo; PART_NUMBER: TMP-871; Company Part Status: Released; CLASS: DISCRETE; Rated Power: 0.1W, 1/10W; Temperature Coefficient: 100ppm/C
RT93 = RES_Dup1: RES SMD 1.8K OHM 0.1% 1/5W 0603; Part Reference: RT93; Manufacturer PN: ERJ-PB3B1801V; Manufacturer: Panasonic Electronic Components; Company Part Status: New; CLASS: DISCRETE; Rated Power: 0.2W, 1/5W; Temperature Coefficient: 50ppm/C
RT94 = RES_Dup1: RES 249K OHM 0.1% 2/5W 1206; Part Reference: RT94; Manufacturer PN: TNPW1206249KBEEA; Manufacturer: Vishay Dale; Company Part Status: New; CLASS: DISCRETE; Rated Power: 0.4W, 2/5W; Temperature Coefficient: 25ppm/C
RT95 = RES_Dup1: RES 249K OHM 0.1% 2/5W 1206; Part Reference: RT95; Manufacturer PN: TNPW1206249KBEEA; Manufacturer: Vishay Dale; Company Part Status: New; CLASS: DISCRETE; Rated Power: 0.4W, 2/5W; Temperature Coefficient: 25ppm/C
RT96 = RES_Dup1: RES 249K OHM 0.1% 2/5W 1206; Part Reference: RT96; Manufacturer PN: TNPW1206249KBEEA; Manufacturer: Vishay Dale; Company Part Status: New; CLASS: DISCRETE; Rated Power: 0.4W, 2/5W; Temperature Coefficient: 25ppm/C
RT97 = RES_Dup1: RES 249K OHM 0.1% 2/5W 1206; Part Reference: RT97; Manufacturer PN: TNPW1206249KBEEA; Manufacturer: Vishay Dale; Company Part Status: New; CLASS: DISCRETE; Rated Power: 0.4W, 2/5W; Temperature Coefficient: 25ppm/C
RT98 = RES_Dup1: RES 249K OHM 0.1% 2/5W 1206; Part Reference: RT98; Manufacturer PN: TNPW1206249KBEEA; Manufacturer: Vishay Dale; Company Part Status: New; CLASS: DISCRETE; Rated Power: 0.4W, 2/5W; Temperature Coefficient: 25ppm/C
RT99 = RES_Dup1: RES 249K OHM 0.1% 2/5W 1206; Part Reference: RT99; Manufacturer PN: TNPW1206249KBEEA; Manufacturer: Vishay Dale; Company Part Status: New; CLASS: DISCRETE; Rated Power: 0.4W, 2/5W; Temperature Coefficient: 25ppm/C
UT1 = AD8615_Dup1: IC OPAMP GP 24MHZ RRO TSOT23-5; Part Reference: UT1; Manufacturer: Analog Devices Inc.; Company Part Status: New; Supply Voltage: 2.7 V - 5.5 V, 1.35 V - 2.75 V
UT2 = AD8615_Dup1: IC OPAMP GP 24MHZ RRO TSOT23-5; Part Reference: UT2; Manufacturer: Analog Devices Inc.; Company Part Status: New; Supply Voltage: 2.7 V - 5.5 V, 1.35 V - 2.75 V
UT12 = AD8615_Dup1: IC OPAMP GP 24MHZ RRO TSOT23-5; Part Reference: UT12; Manufacturer: Analog Devices Inc.; Company Part Status: New; Supply Voltage: 2.7 V - 5.5 V, 1.35 V - 2.75 V
UT18 = AD8615_Dup1: IC OPAMP GP 24MHZ RRO TSOT23-5; Part Reference: UT18; Manufacturer: Analog Devices Inc.; Company Part Status: New; Supply Voltage: 2.7 V - 5.5 V, 1.35 V - 2.75 V

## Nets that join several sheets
0: CAN (CT39.2 UT11.4 UT17.1), Current Sensors (28 pins), Gate Driver Interface (45 pins), LAUNCHPAD (35 pins), Power Supply (55 pins), Temperature Sense (27 pins), Voltage Sense (17 pins)
+1V5REF: Power Supply (CB13.1 RB19.1 UB1.2), Voltage Sense (RT29.1 RT75.1 RT93.1)
+3V3: CAN (CT39.1 UT11.1), Current Sensors (8 pins), Gate Driver Interface (12 pins), LAUNCHPAD (6 pins), Power Supply (7 pins), Temperature Sense (21 pins), Voltage Sense (8 pins)
+3VREF: Current Sensors (RT49.1 RT63.1 RT65.1 RT67.1), Power Supply (CB15.1 RB20.1 UB2.2)
+5V: CAN (UT17.2), Gate Driver Interface (CT65.1 CT66.1 UT22.20 UT23.20), LAUNCHPAD (7 pins), Power Supply (CT63.1 RT109.1 UT26.3)
+12V: Gate Driver Interface (J1.1 J2.1 J3.1), LAUNCHPAD (RT116.1 RT119.1), Power Supply (20 pins)
+15V: Current Sensors (J4.1 J5.1 J6.1), LAUNCHPAD (J10.8), Power Supply (CT72.1 CT85.1 QT1.5 RT138.1)
-15V: Current Sensors (J4.3 J5.3 J6.3), LAUNCHPAD (J10.7), Power Supply (5 pins)
A-Current: Current Sensors (CB7.1 RT15.2), LAUNCHPAD (UT13.30)
A-FAULT: Gate Driver Interface (UT19.3), LAUNCHPAD (UB3.6 UT13.80)
A-LEN-OUT: Gate Driver Interface (UT22.8), LAUNCHPAD (UT13.52)
A-OCEN-OUT: Gate Driver Interface (UT22.9), LAUNCHPAD (UT13.51)
A-PSDIS-OUT: Gate Driver Interface (UT23.4), LAUNCHPAD (UT13.58)
A-RTD: Gate Driver Interface (UT19.5), LAUNCHPAD (UT13.46), Temperature Sense (RT84.1 UT14.2)
A-TEMP: LAUNCHPAD (UT13.69), Temperature Sense (CB11.1 RT24.2)
AHS-PWM: Gate Driver Interface (RB28.1), LAUNCHPAD (UT13.40)
ALS-PWM: Gate Driver Interface (RB29.1), LAUNCHPAD (UT13.39)
B-Current: Current Sensors (CB6.1 RT16.2), LAUNCHPAD (UT13.29)
B-FAULT: Gate Driver Interface (UT19.11), LAUNCHPAD (UB3.3 UT13.79)
B-LEN-OUT: Gate Driver Interface (UT22.6), LAUNCHPAD (UT13.54)
B-OCEN-OUT: Gate Driver Interface (UT22.7), LAUNCHPAD (UT13.53)
B-PSDIS-OUT: Gate Driver Interface (UT23.3), LAUNCHPAD (UT13.59)
B-RTD: Gate Driver Interface (UT19.13), LAUNCHPAD (UT13.45), Temperature Sense (RT85.1 UT15.2)
B-TEMP: LAUNCHPAD (UT13.67), Temperature Sense (CB10.1 RT25.2)
BHS-PWM: Gate Driver Interface (RB30.1), LAUNCHPAD (UT13.38)
BLS-PWM: Gate Driver Interface (RB27.1), LAUNCHPAD (UT13.37)
C-Current: Current Sensors (CB5.1 RT17.2), LAUNCHPAD (UT13.28)
C-FAULT: Gate Driver Interface (UT20.3), LAUNCHPAD (UB3.1 UT13.78)
C-LEN-OUT: Gate Driver Interface (UT22.4), LAUNCHPAD (UT13.57)
C-OCEN-OUT: Gate Driver Interface (UT22.5), LAUNCHPAD (UT13.55)
C-PSDIS-OUT: Gate Driver Interface (UT23.2), LAUNCHPAD (UT13.74)
C-RTD: Gate Driver Interface (UT20.5), LAUNCHPAD (UT13.42), Temperature Sense (RT86.1 UT16.2)
C-TEMP: LAUNCHPAD (UT13.66), Temperature Sense (CB9.1 RT26.2)
CANA-RX: CAN (UT11.2), LAUNCHPAD (UT13.4)
CANA-TX: CAN (UT11.3), LAUNCHPAD (UT13.3)
CASE-TEMP: LAUNCHPAD (UT13.63), Temperature Sense (CB8.1 RT27.2)
CHS-PWM: Gate Driver Interface (RT118.1), LAUNCHPAD (UT13.36)
CLS-PWM: Gate Driver Interface (RT113.1), LAUNCHPAD (UT13.35)
EXT-Current: Current Sensors (CB12.1 RT23.2), LAUNCHPAD (UT13.70)
IEXT-m: Current Sensors (RT36.1 RT38.1), LAUNCHPAD (J10.6)
Shutdown+15V: LAUNCHPAD (UT13.13), Power Supply (RT124.1 RT127.1)
Shutdown-15V: LAUNCHPAD (UT13.12), Power Supply (RT115.1 RT117.1)
Vsense-A: LAUNCHPAD (UT13.27), Voltage Sense (CB4.1 RT18.2)
Vsense-B: LAUNCHPAD (UT13.26), Voltage Sense (CB3.1 RT19.2)
Vsense-C: LAUNCHPAD (UT13.25), Voltage Sense (CB2.1 RT20.2)
Vsense-DC: LAUNCHPAD (UT13.24), Voltage Sense (CB1.1 RT21.2)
